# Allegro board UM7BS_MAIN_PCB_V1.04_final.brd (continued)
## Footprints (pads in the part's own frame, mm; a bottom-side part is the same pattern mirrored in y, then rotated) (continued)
QFN40P600X600-48AN
  oval 0.7x0.2 smd: 1(-2.9,2.2) 2(-2.9,1.8) 3(-2.9,1.4) 4(-2.9,1) 5(-2.9,0.6) 6(-2.9,0.2) 7(-2.9,-0.2) 8(-2.9,-0.6) 9(-2.9,-1) 10(-2.9,-1.4) 11(-2.9,-1.8) 12(-2.9,-2.2) 25(2.9,-2.2) 26(2.9,-1.8) 27(2.9,-1.4) 28(2.9,-1) 29(2.9,-0.6) 30(2.9,-0.2) 31(2.9,0.2) 32(2.9,0.6) 33(2.9,1) 34(2.9,1.4) 35(2.9,1.8) 36(2.9,2.2)
  oval 0.2x0.7 smd: 13(-2.2,-2.9) 14(-1.8,-2.9) 15(-1.4,-2.9) 16(-1,-2.9) 17(-0.6,-2.9) 18(-0.2,-2.9) 19(0.2,-2.9) 20(0.6,-2.9) 21(1,-2.9) 22(1.4,-2.9) 23(1.8,-2.9) 24(2.2,-2.9) 37(2.2,2.9) 38(1.8,2.9) 39(1.4,2.9) 40(1,2.9) 41(0.6,2.9) 42(0.2,2.9) 43(-0.2,2.9) 44(-0.6,2.9) 45(-1,2.9) 46(-1.4,2.9) 47(-1.8,2.9) 48(-2.2,2.9)
  rect 3.6x4.05 smd: E1(0,0)
QFN40P600X600-48N
  oval 0.7x0.2 smd: 1(-2.9,2.2) 2(-2.9,1.8) 3(-2.9,1.4) 4(-2.9,1) 5(-2.9,0.6) 6(-2.9,0.2) 7(-2.9,-0.2) 8(-2.9,-0.6) 9(-2.9,-1) 10(-2.9,-1.4) 11(-2.9,-1.8) 12(-2.9,-2.2) 25(2.9,-2.2) 26(2.9,-1.8) 27(2.9,-1.4) 28(2.9,-1) 29(2.9,-0.6) 30(2.9,-0.2) 31(2.9,0.2) 32(2.9,0.6) 33(2.9,1) 34(2.9,1.4) 35(2.9,1.8) 36(2.9,2.2)
  oval 0.2x0.7 smd: 13(-2.2,-2.9) 14(-1.8,-2.9) 15(-1.4,-2.9) 16(-1,-2.9) 17(-0.6,-2.9) 18(-0.2,-2.9) 19(0.2,-2.9) 20(0.6,-2.9) 21(1,-2.9) 22(1.4,-2.9) 23(1.8,-2.9) 24(2.2,-2.9) 37(2.2,2.9) 38(1.8,2.9) 39(1.4,2.9) 40(1,2.9) 41(0.6,2.9) 42(0.2,2.9) 43(-0.2,2.9) 44(-0.6,2.9) 45(-1,2.9) 46(-1.4,2.9) 47(-1.8,2.9) 48(-2.2,2.9)
  rect 4.3x4.3 smd: E1(0,0)
QFN40P700X700-56AN
  oval 0.7x0.2 smd: 1(-3.4,2.6) 2(-3.4,2.2) 3(-3.4,1.8) 4(-3.4,1.4) 5(-3.4,1) 6(-3.4,0.6) 7(-3.4,0.2) 8(-3.4,-0.2) 9(-3.4,-0.6) 10(-3.4,-1) 11(-3.4,-1.4) 12(-3.4,-1.8) 13(-3.4,-2.2) 14(-3.4,-2.6) 29(3.4,-2.6) 30(3.4,-2.2) 31(3.4,-1.8) 32(3.4,-1.4) 33(3.4,-1) 34(3.4,-0.6) 35(3.4,-0.2) 36(3.4,0.2) 37(3.4,0.6) 38(3.4,1) 39(3.4,1.4) 40(3.4,1.8) 41(3.4,2.2) 42(3.4,2.6)
  oval 0.2x0.7 smd: 15(-2.6,-3.4) 16(-2.2,-3.4) 17(-1.8,-3.4) 18(-1.4,-3.4) 19(-1,-3.4) 20(-0.6,-3.4) 21(-0.2,-3.4) 22(0.2,-3.4) 23(0.6,-3.4) 24(1,-3.4) 25(1.4,-3.4) 26(1.8,-3.4) 27(2.2,-3.4) 28(2.6,-3.4) 43(2.6,3.4) 44(2.2,3.4) 45(1.8,3.4) 46(1.4,3.4) 47(1,3.4) 48(0.6,3.4) 49(0.2,3.4) 50(-0.2,3.4) 51(-0.6,3.4) 52(-1,3.4) 53(-1.4,3.4) 54(-1.8,3.4) 55(-2.2,3.4) 56(-2.6,3.4)
  rect 4.1x4.8 smd: E1(0,0)
QFN40P800X800-64N
  oval 0.8x0.2 smd: 1(-3.9,3) 2(-3.9,2.6) 3(-3.9,2.2) 4(-3.9,1.8) 5(-3.9,1.4) 6(-3.9,1) 7(-3.9,0.6) 8(-3.9,0.2) 9(-3.9,-0.2) 10(-3.9,-0.6) 11(-3.9,-1) 12(-3.9,-1.4) 13(-3.9,-1.8) 14(-3.9,-2.2) 15(-3.9,-2.6) 16(-3.9,-3) 33(3.9,-3) 34(3.9,-2.6) 35(3.9,-2.2) 36(3.9,-1.8) 37(3.9,-1.4) 38(3.9,-1) 39(3.9,-0.6) 40(3.9,-0.2) 41(3.9,0.2) 42(3.9,0.6) 43(3.9,1) 44(3.9,1.4) 45(3.9,1.8) 46(3.9,2.2) 47(3.9,2.6) 48(3.9,3)
  oval 0.2x0.8 smd: 17(-3,-3.9) 18(-2.6,-3.9) 19(-2.2,-3.9) 20(-1.8,-3.9) 21(-1.4,-3.9) 22(-1,-3.9) 23(-0.6,-3.9) 24(-0.2,-3.9) 25(0.2,-3.9) 26(0.6,-3.9) 27(1,-3.9) 28(1.4,-3.9) 29(1.8,-3.9) 30(2.2,-3.9) 31(2.6,-3.9) 32(3,-3.9) 49(3,3.9) 50(2.6,3.9) 51(2.2,3.9) 52(1.8,3.9) 53(1.4,3.9) 54(1,3.9) 55(0.6,3.9) 56(0.2,3.9) 57(-0.2,3.9) 58(-0.6,3.9) 59(-1,3.9) 60(-1.4,3.9) 61(-1.8,3.9) 62(-2.2,3.9) 63(-2.6,3.9) 64(-3,3.9)
  rect 5.7x5.7 smd: E1(0,0)
QFN50P400X400-24BN
  oval 0.8x0.28 smd: 1(-2,1.25) 2(-2,0.75) 3(-2,0.25) 4(-2,-0.25) 5(-2,-0.75) 6(-2,-1.25) 13(2,-1.25) 14(2,-0.75) 15(2,-0.25) 16(2,0.25) 17(2,0.75) 18(2,1.25)
  oval 0.28x0.8 smd: 7(-1.25,-2) 8(-0.75,-2) 9(-0.25,-2) 10(0.25,-2) 11(0.75,-2) 12(1.25,-2) 19(1.25,2) 20(0.75,2) 21(0.25,2) 22(-0.25,2) 23(-0.75,2) 24(-1.25,2)
  rect 2.5x2.5 smd: E1(0,0)
RC0402N
  rect 0.55x0.5 smd: 1(-0.475,0) 2(0.475,0)
RC0603N
  rect 0.8x0.8 smd: 1(-0.75,0) 2(0.75,0)
RC0805N
  rect 1x1.2 smd: 1(-1,0) 2(1,0)
RC1206N
  rect 1.2x1.6 smd: 1(-1.6,0) 2(1.6,0)
SMD-BATTERY-2900P-2N
  rect 3x4.2 smd: 1(14.5,0) 2(-14.5,0)
SMD-CN-50P-20N-H
  oval 0.28x1.25 smd: 1(-4.75,2.325) 2(-4.25,2.325) 3(-3.75,2.325) 4(-3.25,2.325) 5(-2.75,2.325) 6(-2.25,2.325) 7(-1.75,2.325) 8(-1.25,2.325) 9(-0.75,2.325) 10(-0.25,2.325) 11(0.25,2.325) 12(0.75,2.325) 13(1.25,2.325) 14(1.75,2.325) 15(2.25,2.325) 16(2.75,2.325) 17(3.25,2.325) 18(3.75,2.325) 19(4.25,2.325) 20(4.75,2.325)
  rect 2x3.4 smd: E1(-6.44,0.4) E2(6.44,0.4)
SMD-CN-100P-2N-V-CB
  rect 0.6x1.5 smd: 1(0.5,2.55) 2(-0.5,2.55)
  rect 1.2x1.8 smd: E1(-1.8,0) E2(1.8,0)
SMD-CN-100P-4N-V-CB
  rect 0.6x1.5 smd: 1(1.5,2.55) 2(0.5,2.55) 3(-0.5,2.55) 4(-1.5,2.55)
  rect 1.2x1.8 smd: E1(-2.8,0) E2(2.8,0)
SMD-CN-100P-6N-H
  rect 0.6x1.55 smd: 1(-2.5,3.875) 2(-1.5,3.875) 3(-0.5,3.875) 4(0.5,3.875) 5(1.5,3.875) 6(2.5,3.875)
  rect 1.2x2 smd: E1(-3.8,0) E2(3.8,0)
SMD-CN-100P-40AN-H
  rect 0.6x1.6 smd: 1(-9.5,-2.9) 2(-8.5,-2.9) 3(-7.5,-2.9) 4(-6.5,-2.9) 5(-5.5,-2.9) 6(-4.5,-2.9) 7(-3.5,-2.9) 8(-2.5,-2.9) 9(-1.5,-2.9) 10(-0.5,-2.9) 11(0.5,-2.9) 12(1.5,-2.9) 13(2.5,-2.9) 14(3.5,-2.9) 15(4.5,-2.9) 16(5.5,-2.9) 17(6.5,-2.9) 18(7.5,-2.9) 19(8.5,-2.9) 20(9.5,-2.9) 21(9.5,2.9) 22(8.5,2.9) 23(7.5,2.9) 24(6.5,2.9) 25(5.5,2.9) 26(4.5,2.9) 27(3.5,2.9) 28(2.5,2.9) 29(1.5,2.9) 30(0.5,2.9) 31(-0.5,2.9) 32(-1.5,2.9) 33(-2.5,2.9) 34(-3.5,2.9) 35(-4.5,2.9) 36(-5.5,2.9) 37(-6.5,2.9) 38(-7.5,2.9) 39(-8.5,2.9) 40(-9.5,2.9)
  rect 1.5x2.3 smd: E1(-11.5,-1.3) E2(11.5,-1.3)
SMD-CN-125P-2WBN
  rect 0.8x1.5 smd: 1(-0.625,2.49) 2(0.625,2.49)
  rect 2x2.5 smd: E1(-3.175,0) E2(3.175,0)
SMD-CN-200P-8N
  rect 1x3 smd: 1(-3,-2.25) 2(-3,2.25) 3(-1,-2.25) 4(-1,2.25) 5(1,-2.25) 6(1,2.25) 7(3,-2.25) 8(3,2.25)
SMD-DDR-60X1020P-204N-R
  round 1.1 hole 1.1 unplated: (-33.4,0)
  round 1.6 hole 1.6 unplated: (33.4,0)
  rect 0.35x2 smd: 1(31.65,4.1) 2(31.35,-4.1) 3(31.05,4.1) 4(30.75,-4.1) 5(30.45,4.1) 6(30.15,-4.1) 7(29.85,4.1) 8(29.55,-4.1) 9(29.25,4.1) 10(28.95,-4.1) 11(28.65,4.1) 12(28.35,-4.1) 13(28.05,4.1) 14(27.75,-4.1) 15(27.45,4.1) 16(27.15,-4.1) 17(26.85,4.1) 18(26.55,-4.1) 19(26.25,4.1) 20(25.95,-4.1) 21(25.65,4.1) 22(25.35,-4.1) 23(25.05,4.1) 24(24.75,-4.1) 25(24.45,4.1) 26(24.15,-4.1) 27(23.85,4.1) 28(23.55,-4.1) 29(23.25,4.1) 30(22.95,-4.1) 31(22.65,4.1) 32(22.35,-4.1) 33(22.05,4.1) 34(21.75,-4.1) 35(21.45,4.1) 36(21.15,-4.1) 37(20.85,4.1) 38(20.55,-4.1) 39(20.25,4.1) 40(19.95,-4.1) 41(19.65,4.1) 42(19.35,-4.1) 43(19.05,4.1) 44(18.75,-4.1) 45(18.45,4.1) 46(18.15,-4.1) 47(17.85,4.1) 48(17.55,-4.1) 49(17.25,4.1) 50(16.95,-4.1) 51(16.65,4.1) 52(16.35,-4.1) 53(16.05,4.1) 54(15.75,-4.1) 55(15.45,4.1) 56(15.15,-4.1) 57(14.85,4.1) 58(14.55,-4.1) 59(14.25,4.1) 60(13.95,-4.1) 61(13.65,4.1) 62(13.35,-4.1) 63(13.05,4.1) 64(12.75,-4.1) 65(12.45,4.1) 66(12.15,-4.1) 67(11.85,4.1) 68(11.55,-4.1) 69(11.25,4.1) 70(10.95,-4.1) 71(10.65,4.1) 72(10.35,-4.1) 73(7.65,4.1) 74(7.35,-4.1) 75(7.05,4.1) 76(6.75,-4.1) 77(6.45,4.1) 78(6.15,-4.1) 79(5.85,4.1) 80(5.55,-4.1) 81(5.25,4.1) 82(4.95,-4.1) 83(4.65,4.1) 84(4.35,-4.1) 85(4.05,4.1) 86(3.75,-4.1) 87(3.45,4.1) 88(3.15,-4.1) 89(2.85,4.1) 90(2.55,-4.1) 91(2.25,4.1) 92(1.95,-4.1) 93(1.65,4.1) 94(1.35,-4.1) 95(1.05,4.1) 96(0.75,-4.1) 97(0.45,4.1) 98(0.15,-4.1) 99(-0.15,4.1) 100(-0.45,-4.1) 101(-0.75,4.1) 102(-1.05,-4.1) 103(-1.35,4.1) 104(-1.65,-4.1) 105(-1.95,4.1) 106(-2.25,-4.1) 107(-2.55,4.1) 108(-2.85,-4.1) 109(-3.15,4.1) 110(-3.45,-4.1) 111(-3.75,4.1) 112(-4.05,-4.1) 113(-4.35,4.1) 114(-4.65,-4.1) 115(-4.95,4.1) 116(-5.25,-4.1) 117(-5.55,4.1) 118(-5.85,-4.1) 119(-6.15,4.1) 120(-6.45,-4.1) 121(-6.75,4.1) 122(-7.05,-4.1) 123(-7.35,4.1) 124(-7.65,-4.1) 125(-7.95,4.1) 126(-8.25,-4.1) 127(-8.55,4.1) 128(-8.85,-4.1) 129(-9.15,4.1) 130(-9.45,-4.1) 131(-9.75,4.1) 132(-10.05,-4.1) 133(-10.35,4.1) 134(-10.65,-4.1) 135(-10.95,4.1) 136(-11.25,-4.1) 137(-11.55,4.1) 138(-11.85,-4.1) 139(-12.15,4.1) 140(-12.45,-4.1) 141(-12.75,4.1) 142(-13.05,-4.1) 143(-13.35,4.1) 144(-13.65,-4.1) 145(-13.95,4.1) 146(-14.25,-4.1) 147(-14.55,4.1) 148(-14.85,-4.1) 149(-15.15,4.1) 150(-15.45,-4.1) 151(-15.75,4.1) 152(-16.05,-4.1) 153(-16.35,4.1) 154(-16.65,-4.1) 155(-16.95,4.1) 156(-17.25,-4.1) 157(-17.55,4.1) 158(-17.85,-4.1) 159(-18.15,4.1) 160(-18.45,-4.1) 161(-18.75,4.1) 162(-19.05,-4.1) 163(-19.35,4.1) 164(-19.65,-4.1) 165(-19.95,4.1) 166(-20.25,-4.1) 167(-20.55,4.1) 168(-20.85,-4.1) 169(-21.15,4.1) 170(-21.45,-4.1) 171(-21.75,4.1) 172(-22.05,-4.1) 173(-22.35,4.1) 174(-22.65,-4.1) 175(-22.95,4.1) 176(-23.25,-4.1) 177(-23.55,4.1) 178(-23.85,-4.1) 179(-24.15,4.1) 180(-24.45,-4.1) 181(-24.75,4.1) 182(-25.05,-4.1) 183(-25.35,4.1) 184(-25.65,-4.1) 185(-25.95,4.1) 186(-26.25,-4.1) 187(-26.55,4.1) 188(-26.85,-4.1) 189(-27.15,4.1) 190(-27.45,-4.1) 191(-27.75,4.1) 192(-28.05,-4.1) 193(-28.35,4.1) 194(-28.65,-4.1) 195(-28.95,4.1) 196(-29.25,-4.1) 197(-29.55,4.1) 198(-29.85,-4.1) 199(-30.15,4.1) 200(-30.45,-4.1) 201(-30.75,4.1) 202(-31.05,-4.1) 203(-31.35,4.1) 204(-31.65,-4.1)
  rect 3.6x4.6 smd: E1(-32.8,-12) E2(32.8,-12)
SMD-M2PCIE-50X750P-75AN
  round 0.254 hole 1.092 unplated: (-10,-1.499)
  round 0.254 hole 1.6 unplated: (10,-1.499)
  rect 0.305x1.575 smd: 1(-9.25,3.763) 2(-9,-3.763) 3(-8.75,3.763) 4(-8.5,-3.763) 5(-8.25,3.763) 6(-8,-3.763) 7(-7.75,3.763) 8(-7.5,-3.763) 9(-7.25,3.763) 10(-7,-3.763) 11(-6.75,3.763) 12(-6.5,-3.763) 13(-6.25,3.763) 14(-6,-3.763) 15(-5.75,3.763) 16(-5.5,-3.763) 17(-5.25,3.763) 18(-5,-3.763) 19(-4.75,3.763) 20(-4.5,-3.763) 21(-4.25,3.763) 22(-4,-3.763) 23(-3.75,3.763) 24(-3.5,-3.763) 25(-3.25,3.763) 26(-3,-3.763) 27(-2.75,3.763) 28(-2.5,-3.763) 29(-2.25,3.763) 30(-2,-3.763) 31(-1.75,3.763) 32(-1.5,-3.763) 33(-1.25,3.763) 34(-1,-3.763) 35(-0.75,3.763) 36(-0.5,-3.763) 37(-0.25,3.763) 38(0,-3.763) 39(0.25,3.763) 40(0.5,-3.763) 41(0.75,3.763) 42(1,-3.763) 43(1.25,3.763) 44(1.5,-3.763) 45(1.75,3.763) 46(2,-3.763) 47(2.25,3.763) 48(2.5,-3.763) 49(2.75,3.763) 50(3,-3.763) 51(3.25,3.763) 52(3.5,-3.763) 53(3.75,3.763) 54(4,-3.763) 55(4.25,3.763) 56(4.5,-3.763) 57(4.75,3.763) 58(5,-3.763) 59(5.25,3.763) 60(5.5,-3.763) 61(5.75,3.763) 62(6,-3.763) 63(6.25,3.763) 64(6.5,-3.763) 65(6.75,3.763) 66(7,-3.763) 67(7.25,3.763) 68(7.5,-3.763) 69(7.75,3.763) 70(8,-3.763) 71(8.25,3.763) 72(8.5,-3.763) 73(8.75,3.763) 74(9,-3.763) 75(9.25,3.763)
  rect 1.219x2.769 smd: E1(-10.39,3.001) E2(10.39,3.001)
SMD-M2PCIE-50X750P-75BN
  round 0.254 hole 1.092 unplated: (-10,-1.499)
  round 0.254 hole 1.6 unplated: (10,-1.499)
  rect 0.305x1.575 smd: 1(-9.25,3.763) 2(-9,-3.763) 3(-8.75,3.763) 4(-8.5,-3.763) 5(-8.25,3.763) 6(-8,-3.763) 7(-7.75,3.763) 8(-7.5,-3.763) 9(-7.25,3.763) 10(-7,-3.763) 11(-6.75,3.763) 12(-6.5,-3.763) 13(-6.25,3.763) 14(-6,-3.763) 15(-5.75,3.763) 16(-5.5,-3.763) 17(-5.25,3.763) 18(-5,-3.763) 19(-4.75,3.763) 20(-4.5,-3.763) 21(-4.25,3.763) 22(-4,-3.763) 23(-3.75,3.763) 24(-3.5,-3.763) 25(-3.25,3.763) 26(-3,-3.763) 27(-2.75,3.763) 28(-2.5,-3.763) 29(-2.25,3.763) 30(-2,-3.763) 31(-1.75,3.763) 32(-1.5,-3.763) 33(-1.25,3.763) 34(-1,-3.763) 35(-0.75,3.763) 36(-0.5,-3.763) 37(-0.25,3.763) 38(0,-3.763) 39(0.25,3.763) 40(0.5,-3.763) 41(0.75,3.763) 42(1,-3.763) 43(1.25,3.763) 44(1.5,-3.763) 45(1.75,3.763) 46(2,-3.763) 47(2.25,3.763) 48(2.5,-3.763) 49(2.75,3.763) 50(3,-3.763) 51(3.25,3.763) 52(3.5,-3.763) 53(3.75,3.763) 54(4,-3.763) 55(4.25,3.763) 56(4.5,-3.763) 57(4.75,3.763) 58(5,-3.763) 67(7.25,3.763) 68(7.5,-3.763) 69(7.75,3.763) 70(8,-3.763) 71(8.25,3.763) 72(8.5,-3.763) 73(8.75,3.763) 74(9,-3.763) 75(9.25,3.763)
  rect 1.219x2.769 smd: E1(-10.39,3.001) E2(10.39,3.001)
SMD-SATA-127P-22AN-L-KX
  round 1.4 hole 1.4 unplated: (-17,-1.35) (17,-1.35)
  oval 1.6x3.3 hole 1x2.6: E1(-18.71,1.05) E2(18.71,1.05)
  rect 0.9x2.6 smd: P1(-1.905,1.05) P2(-0.635,1.05) P3(0.635,1.05) P4(1.905,1.05) P5(3.175,1.05) P6(4.445,1.05) P7(5.715,1.05) P8(6.985,1.05) P9(8.255,1.05) P10(9.525,1.05) P11(10.795,1.05) P12(12.065,1.05) P13(13.335,1.05) P14(14.605,1.05) P15(15.875,1.05) S1(-15.875,1.05) S2(-14.605,1.05) S3(-13.335,1.05) S4(-12.065,1.05) S5(-10.795,1.05) S6(-9.525,1.05) S7(-8.255,1.05)
SMD-SD-250P-9N
  round 1 hole 1 unplated: (-11.45,6.5)
  round 1.5 hole 1.5 unplated: (9.53,6.5)
  rect 0.7x1.9 smd: 1(6.8,9.25) 2(4.3,9.25) 3(1.8,9.25) 4(-0.7,9.25) 5(-3.2,9.25) 6(-5.7,9.25) 7(-8.2,9.25) 8(-9.83,9.25) 9(9.3,9.25) 10(-12.37,9.25) 11(-11.08,9.25)
  rect 1.6x1.6 smd: E1(-14.05,7.55) E2(11.75,7.55) E3(-14.05,-6.65) E4(14.05,-6.65)
SMD-TRANSF-127P-16N
  rect 1.9x0.8 smd: 1(-4.2,4.445) 2(-4.2,3.175) 3(-4.2,1.905) 4(-4.2,0.635) 5(-4.2,-0.635) 6(-4.2,-1.905) 7(-4.2,-3.175) 8(-4.2,-4.445) 9(4.2,-4.445) 10(4.2,-3.175) 11(4.2,-1.905) 12(4.2,-0.635) 13(4.2,0.635) 14(4.2,1.905) 15(4.2,3.175) 16(4.2,4.445)
SMD-USB-100P-9AN
  rect 0.7x1.65 smd: 1(-3,1) 2(-1,1) 3(1,1) 4(3,1) 5(4,1) 6(2,1) 7(0,1) 8(-2,1) 9(-4,1)
  oval 1.6x3.4 hole 0.6x2.4: E1(-7.9,0) E2(7.9,0)
  rect 1.7x2.3 smd: E3(-7.68,-4.2) E4(7.68,-4.2)
SOD0806N
  rect 0.4x0.35 smd: N(-0.45,0) P(0.45,0)
SOD1713N
  rect 0.8x0.6 smd: N(1.25,0) P(-1.25,0)
SOD2514N
  rect 1.2x0.5 smd: N(-1.15,0) P(1.15,0)
SOD2818N
  rect 2.2x1.4 smd: N(1,0)
  rect 0.9x1.4 smd: P(-1.65,0)
SOD5225N
  rect 2x2 smd: N(-2.095,0) P(2.095,0)
SOD5336N
  rect 2.5x2.3 smd: N(2.15,0) P(-2.15,0)
SOIC127P600-8N
  rect 1.9x0.6 smd: 1(-2.55,1.905) 2(-2.55,0.635) 3(-2.55,-0.635) 4(-2.55,-1.905) 5(2.55,-1.905) 6(2.55,-0.635) 7(2.55,0.635) 8(2.55,1.905)
SOIC127P800-8N
  rect 1.8x0.6 smd: 1(-3.6,1.905) 2(-3.6,0.635) 3(-3.6,-0.635) 4(-3.6,-1.905) 5(3.6,-1.905) 6(3.6,-0.635) 7(3.6,0.635) 8(3.6,1.905)
SON35P100-8N
  oval 0.55x0.2 smd: 1(-0.46,0.525) 2(-0.46,0.174) 3(-0.46,-0.176) 4(-0.46,-0.526) 5(0.46,-0.526) 6(0.46,-0.176) 7(0.46,0.174) 8(0.46,0.525)
SON50P200X200-8N
  oval 0.6x0.25 smd: 1(-1,0.749) 2(-1,0.249) 3(-1,-0.251) 4(-1,-0.751) 5(1,-0.751) 6(1,-0.251) 7(1,0.249) 8(1,0.749)
  rect 0.9x1.6 smd: E1(0,0)
SON127P500X600-8AN
  oval 0.9x0.6 smd: 1(-2.85,1.905) 2(-2.85,0.635) 3(-2.85,-0.635) 4(-2.85,-1.905) 5(2.85,-1.905) 6(2.85,-0.635) 7(2.85,0.635) 8(2.85,1.905)
  rect 3.4x4 smd: E1(0,0)
SOP35P100-3N
  rect 0.3x0.3 smd: 1(-0.35,-0.425) 2(0.35,-0.425) 3(0,0.425)
SOT65P190-5N
  oval 1.1x0.35 smd: 1(-0.95,0.65) 2(-0.95,0) 3(-0.95,-0.65) 4(0.95,-0.65) 5(0.95,0.65)
SOT65P210-3N
  rect 1.2x0.45 smd: 1(-0.9,0.65) 2(-0.9,-0.65) 3(0.9,0)
SOT65P210-5N
  rect 1.1x0.4 smd: 1(-0.95,0.65) 2(-0.95,0) 3(-0.95,-0.65) 4(0.95,-0.65) 5(0.95,0.65)
SOT65P210-6N
  rect 1.08x0.35 smd: 1(-1,0.65) 2(-1,0) 3(-1,-0.65) 4(1,-0.65) 5(1,0) 6(1,0.65)
SOT95P240-3N
  rect 1.4x0.6 smd: 1(-1,0.95) 2(-1,-0.95) 3(1,0)
SOT95P280-3N
  rect 1.35x0.6 smd: 1(-1.25,0.95) 2(-1.25,-0.95) 3(1.25,0)
SOT95P280-5N
  rect 1.3x0.6 smd: 1(-1.25,0.95) 2(-1.25,0) 3(-1.25,-0.95) 4(1.25,-0.95) 5(1.25,0.95)
SOT229P990-3N
  rect 1x2.2 smd: 1(-2.29,-3.35) 2(2.29,-3.35)
  rect 5.5x5.3 smd: 3(0,3.15)
SSOP65P780-28N
  rect 1.4x0.3 smd: 1(-3.35,4.225) 2(-3.35,3.575) 3(-3.35,2.925) 4(-3.35,2.275) 5(-3.35,1.625) 6(-3.35,0.975) 7(-3.35,0.325) 8(-3.35,-0.325) 9(-3.35,-0.975) 10(-3.35,-1.625) 11(-3.35,-2.275) 12(-3.35,-2.925) 13(-3.35,-3.575) 14(-3.35,-4.225) 15(3.35,-4.225) 16(3.35,-3.575) 17(3.35,-2.925) 18(3.35,-2.275) 19(3.35,-1.625) 20(3.35,-0.975) 21(3.35,-0.325) 22(3.35,0.325) 23(3.35,0.975) 24(3.35,1.625) 25(3.35,2.275) 26(3.35,2.925) 27(3.35,3.575) 28(3.35,4.225)
SW_330X390P_4N
  rect 1x0.7 smd: 1(-1.95,1.65) 2(-1.95,-1.65) 3(1.95,1.65) 4(1.95,-1.65)
TDFN50P300X300-10N
  oval 0.65x0.25 smd: 1(-1.325,1) 2(-1.325,0.5) 3(-1.325,0) 4(-1.325,-0.5) 5(-1.325,-1) 6(1.325,-1) 7(1.325,-0.5) 8(1.325,0) 9(1.325,0.5) 10(1.325,1)
  rect 1.5x2.5 smd: E1(0,0)
TEST120
  round 1.2 smd: 1(0,0)
TH-CN-200P-2N-H
  round 1.4 hole 0.8: 1(-1,0) 2(1,0)
TH-DCIN-540P-3N
  round 1.3 hole 1.3 unplated: (-4.25,4.5) (4.25,-4.5)
  oval 2x3.5 hole 0.9x2.5: B(-4,1)
  oval 3.5x2 hole 2.5x0.9: C(-2,-4.4) D(2.6,-2)
TH-EARPHONE-330X400P-5N
  round 1.1 hole 1.1 unplated: (0,-2.55)
  oval 2.1x1.2 hole 1.5x0.6: 2(0,2.55)
  oval 1.2x2.1 hole 0.6x1.5: 3(-4,1.65) 4(4,1.65) 5(-2.5,-1.65) 6(2.5,-1.65)
TH-RJ45-127P-8N
  round 3.2 hole 3.2 unplated: (-5.715,1.1) (5.715,1.1)
  round 1.05 hole 0.7: 1(-4.445,7.45) 2(-3.175,7.45) 3(-1.905,7.45) 4(-0.635,7.45) 5(0.635,7.45) 6(1.905,7.45) 7(3.175,7.45) 8(4.445,7.45)
  round 2.6 hole 1.6: E1(-7.875,4.99) E2(7.875,4.99)
TH-SW-420P-2N
  round 1 hole 1 unplated: (-1.15,0) (1.15,0)
  rect 1.2x1.5 smd: 1(-2.1,1) 2(2.1,1)
  rect 1.3x1.2 smd: E1(-3.525,-0.8) E2(3.525,-0.8)
TH-USB-250PX200P-4BN
  round 1.55 hole 0.95: 1(-3.5,0.81) 2(-1,0.81) 3(1,0.81) 4(3.5,0.81)
  oval 1.2x2.1 hole 0.6x1.5: E1(-6.4,0.21) E2(6.4,0.21)
THR-CPR50-630X1100N
  round 1.5 hole 0.7: 1(-1.25,0) 2(1.25,0)
TSSOP65P640-16AN
  rect 1.6x0.35 smd: 1(-3,2.275) 2(-3,1.625) 3(-3,0.975) 4(-3,0.325) 5(-3,-0.325) 6(-3,-0.975) 7(-3,-1.625) 8(-3,-2.275) 9(3,-2.275) 10(3,-1.625) 11(3,-0.975) 12(3,-0.325) 13(3,0.325) 14(3,0.975) 15(3,1.625) 16(3,2.275)
  rect 3x2.8 smd: E1(0,0)
unnamed
  round 2 hole 2 unplated: (0,0)
UQFN40P200X170-12N
  oval 0.7x0.4 smd: 1(-0.7,0.9)
  oval 0.7x0.2 smd: 2(-0.7,0.401) 3(-0.7,0.002) 4(-0.7,-0.399) 5(-0.7,-0.799) 7(0.7,-0.799) 8(0.7,-0.399) 9(0.7,0.002) 10(0.7,0.401) 11(0.7,0.801)
  oval 0.2x0.7 smd: 6(0,-0.85) 12(0,0.85)
VSOP127P790-8N
  rect 1.6x0.6 smd: 1(-3.44,1.905) 2(-3.44,0.635) 3(-3.44,-0.635) 4(-3.44,-1.905) 5(3.44,-1.905) 6(3.44,-0.635) 7(3.44,0.635) 8(3.44,1.905)

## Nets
3.3V_IN: C149.2 FB1.2 FB2.1 R172.1 R173.2 R175.1 U9.24(V33)
+V1.2A: C201.2 R670.1 U11.49(LDOA3)
+V1.05A: C42.2 C43.2 C44.2 C45.2 C46.2 C47.2 C48.2 C52.2 C53.2 C54.1 C55.1 C56.2 C57.2 C58.2 C68.2 C69.2 C70.2 C71.2 C72.2 C73.1 C74.1 C75.1 C76.1 C77.1 C106.2 C239.1 C240.1 C241.1 C242.1 CP3.1 L7.1 R111.2 R843.1 U1.AA32(UNCORE_V1P15_S0IX1) U1.AA33(UNCORE_V1P15_S0IX2) U1.AA35(UNCORE_V1P15_S0IX3) U1.AA36(UNCORE_V1P15_S0IX4) U1.AC32(UNCORE_V1P15_S0IX5) U1.AM21(DDR_V1P05A_G31) U1.AM22(DDR_V1P05A_G32) U1.AM32(DDR_V1P05A_G33) U1.AM33(DDR_V1P05A_G34) U1.AN22(DDR_V1P05A_G35) U1.AN32(DDR_V1P05A_G36) U1.G10(FUSE0_V1P05A_G3) U1.H10(FUSE1_V1P05A_G4) U1.N18(FUSE3_V1P05A_G5) U1.U19(FUSE_V1P05A_G3) U1.U22(SATA_V1P05A_G31) U1.U24(SATA_V1P05A_G32) U1.U27(USB3_V1P05A_G31) U1.V18(ICLK_GND_OFF1) U1.V19(ICLK_GND_OFF2) U1.V22(PCIE_V1P05A_G31) U1.V24(PCIE_V1P05A_G32) U1.V27(USB3_V1P05A_G32) U1.V29(USBSSIC_V1P05A_G3) U1.V33(UNCORE_V1P15_S0IX6) U1.Y30(UNCORE_V1P15_S0IX7) U1.Y32(UNCORE_V1P15_S0IX8) U1.Y33(UNCORE_V1P15_S0IX9) U1.Y35(UNCORE_V1P15_S0IX10)
+V1.5S: C362.2 C557.1 R137.1 R330.2 R556.2 U46.4(VOUT)
+V1.5S_AUDIO: FB11.2 R330.1 R344.2
+V1.8A: C9.2 C14.1 C21.1 C96.2 C97.2 C103.2 C107.2 C108.2 C109.2 C110.2 C111.2 C194.2 C234.2 C249.1 C250.1 C251.1 C252.1 C413.1 C418.1 C420.1 C435.1 C527.1 C2837.1 D1.P L8.1 Q6.1(G) Q7.1(G) Q52.1(G) Q53.1(G) R14.2 R18.2 R26.2 R27.2 R28.2 R29.2 R42.1 R43.2 R51.1 R53.1 R54.1 R55.2 R58.1 R61.1 R62.2 R64.2 R65.2 R66.1 R67.2 R68.2 R71.1 R73.2 R88.2 R89.2 R90.2 R108.2 R115.2 R119.2 R122.2 R125.1 R127.1 R134.2 R138.1 R141.2 R163.1 R169.1 R196.2 R227.2 R228.2 R229.2 R234.1 R386.1 R391.1 R401.1 R402.1 R409.2 R414.2 R416.2 R427.1 R434.2 R441.2 R572.2 R573.2 R844.1 R3108.2 U1.AA29(USB_V1P8A_G3) U1.AD33(GPIO_V1P8A_G31) U1.AF33(GPIO_V1P8A_G32) U1.AK18(GPIO_V1P8A_G33) U1.AK19(GPIO_V1P8A_G34) U1.U16(FUSE_V1P8A_G3) U1.Y18(GPIO_V1P8A_G35) U3.1(VIN1) U3.2(VIN2) U5.1(VCCA) U6.1(VCCA) U11.18(PVINSWB1_B2) U11.50(PVINLDOA2_A3) U29.1(VCCA) U30.1(VCCA) U32.1(VCCA) U46.3(VIN) U53.7(VIN1) U53.8(VIN2) U53.9(VIN3) U2525.7(VIN1) U2525.8(VIN2) U2525.9(VIN3)
+V1.8A_SPI: C8.2 D1.N R40.2 R41.2 R42.2 R568.2 U2.8(VCC) U3.7(VOUT2) U3.8(VOUT1) U4.8(VCC)
+V1.8S: C235.2 D44.P FB10.2 R22.2 R72.2 R343.2 R575.1 U11.19(SWB2)
+V1.8U: C233.2 U11.17(SWB1)
+V1.15A: C59.2 C60.2 C61.2 C62.2 C63.2 C64.2 C65.2 C66.2 C67.2 C2835.1 R213.2 R746.2 U1.AJ35(FUSE_V1P15_S0IX1) U1.AK21(DDI_V1P15_S0IX1) U1.AK30(CORE_V1P15_S0IX1) U1.AK33(FUSE_V1P15_S0IX2) U1.AK35(CORE_V1P15_S0IX2) U1.AK36(CORE_V1P15_S0IX3) U1.AM19(DDI_V1P15_S0IX2) U1.AM29(CORE_V1P15_S0IX4) U2525.1(VOUT1) U2525.2(VOUT2) U2525.3(VOUT3)
+V1.15S: C193.2 R213.1 U11.51(LDOA2)
+V1.24A: C78.2 C79.2 C83.2 C84.2 C85.2 C86.2 C89.2 C90.2 C95.2 C2834.1 R136.1 R139.1 R142.1 R670.2 R3107.1 U1.AC30(CORE_VSFR_G37) U1.AC36(CORE_VSFR_G31) U1.AD35(CORE_VSFR_G32) U1.AD38(CORE_VSFR_G33) U1.AF35(CORE_VSFR_G34) U1.H44(USB_VDDQ_G31) U1.P38(CORE_VSFR_G35) U1.U35(USB_VDDQ_G32) U1.V30(CORE_VSFR_G36) U1.V35(USB_VDDQ_G33) U1.V36(DDI_VDDQ_G31) U1.Y25(ICLK_VSFR_G31) U1.Y27(ICLK_VSFR_G32) U1.Y36(DDI_VDDQ_G32) U53.1(VOUT1) U53.2(VOUT2) U53.3(VOUT3)
+V1P8A_EMMC: C144.1 C145.1 D44.N R163.2 R575.2 R576.1 U8.AA3(VDD4) U8.AA5(VDD5) U8.K6(VDD1) U8.W4(VDD2) U8.Y4(VDD3)
+V2P8A_EMMC: C141.1 C142.1 R155.1 R574.1 U8.M6(VDDF1) U8.N5(VDDF2) U8.T10(VDDF3) U8.U9(VDDF4)
+V3.3A: C22.1 C113.1 C173.1 C174.1 C238.1 C257.1 C265.1 C332.1 C333.1 C405.1 C411.1 C414.1 C419.1 C421.1 CP7.1 CP8.1 D8.P D27.P D30.P FB37.1 FB38.1 L2.2 LED2.1(P) Q21.5(D1) Q21.6(D2) Q21.7(D3) Q21.8(D4) R113.2 R118.2 R123.2 R143.2 R144.2 R172.2 R183.2 R188.1 R295.2 R296.2 R374.2 R375.2 R406.1 R410.2 R413.1 R554.2 R587.1 R592.2 R3105.1 R3109.1 U6.11(VCCB) U7.5(VCC) U11.32(PVINSWA1) U21.5(VIN) U27.5(VCC) U28.5(VIN) U29.6(VCCB) U30.11(VCCB) U32.11(VCCB) U44.5(VIN)
+V3.3A_KBC: C415.2 C416.2 D12.P D29.N D30.N D31.N FB15.1 R385.1 R388.1 R389.2 R392.1 R394.1 R396.1 R399.1 R405.1 R408.1 R445.2 R456.1 R457.2 R591.1 R828.2 U31.26(VSTBY6) U31.50(VSTBY5) U31.92(VSTBY4) U31.114(VSTBY3) U31.121(VSTBY2) U31.127(VSTBY1(PLL))
+V3.3A_LDO: C184.2 U11.54(LDO3P3)
+V3.3A_PRIME: C101.2 C102.2 C104.2 C266.2 C267.1 R133.2 R155.2 R231.2 U1.B22(USB_V3P3A_G31) U1.C23(USB_V3P3A_G32) U1.D4(RTC_V3P3A_G51) U1.E3(RTC_V3P3A_G52) U44.1(VOUT)
+V3.3A_RTC: C98.2 C488.2 D26.N D27.N R79.2 R83.2 R387.1 U1.B6(RTC_V3P3RTC_G51) U1.C5(RTC_V3P3RTC_G52)
+V3.3A_SW: C243.2 R140.2 R207.2 R231.1 R558.2 U11.31(SWA1)
+V3.3A_WIFI: C400.1 C401.2 C402.2 C409.2 C410.1 C799.2 C800.2 C801.2 CN26.2(3.3V_2) CN26.4(3.3V_4) CN26.72(3.3V_72) CN26.74(3.3V_74) Q41.1(G) R374.1 R789.1 U28.1(VOUT)
+V3.3AVCC: C417.1 FB15.2 U31.74(AVCC)
+V3.3S: C15.1 C114.2 C115.2 C258.2 C259.1 C374.1 C395.2 C426.2 CN1.199(VDDSPD) CN11.1 CN11.2 CN11.14 CN11.15 CN11.18 FB4.1 FB6.2 FB12.2 FB19.2 FB25.2 Q21.1(S1) Q21.2(S2) Q21.3(S3) R69.1 R70.1 R126.2 R146.1 R147.2 R247.2 R251.1 R253.1 R294.1 R305.2 R350.1 R351.1 R353.1 R364.1 R365.1 R536.1 R537.1 R539.1 R540.1 R574.2 R584.1 R586.1 R590.2 U5.8(VCCB) U26.5(VCC) U33.5(VCC) U42.5(VCC)
+V3.3S_AUDIO: C367.2 C368.2 FB12.1 FB13.1 R346.1 U25.36(CPVDD)
+V3.3S_MSATA: C313.2 C314.2 C315.2 C316.2 CN9.2(3.3V_2) CN9.4(3.3V_4) CN9.12(3.3V_12) CN9.14(3.3V_14) CN9.16(3.3V_16) CN9.18(3.3V_18) CN9.70(3.3V_70) CN9.72(3.3V_72) CN9.74(3.3V_74) FB25.1
+V5_AVDD: C369.2 C370.1 D43.N FB8.1 R349.2 R355.2 U25.26(AVDD1)
+V5_PVDD: C380.2 C381.1 C382.2 C383.1 FB9.1 U25.41(PVDD1) U25.46(PVDD2)
+V5A: C11.2 C167.1 C168.1 C180.1 C214.1 C218.1 C236.1 C237.1 C253.1 C436.1 C437.1 C444.1 C449.1 C454.1 C829.1 C830.1 C831.1 C2836.1 CP5.1 CP6.1 D4.1(X1) F2.1 F3.1 F4.1 F5.1 L1.1 Q18.5(D1) Q18.6(D2) Q18.7(D3) Q18.8(D4) R171.2 R174.1 R177.1 R180.1 R475.1 R482.1 R487.1 R492.1 U3.4(VBIAS) U10.14(VO1) U11.11(PVIN3) U11.21(PVIN5) U11.24(PVIN4) U11.57(V5ANA) U35.5(VIN) U38.5(VIN) U39.5(VIN) U40.5(VIN) U53.10(VCNTL) U2525.10(VCNTL)
+V5A_LDO: C182.2 C212.2 C215.1 U11.8(DRV5V_2_EC) U11.38(DRV5V_1_6) U11.56(LDO5P0)
+V5S: C254.2 C255.1 C360.1 C361.1 D43.P FB8.2 FB9.2 FB24.2 FB27.2 Q18.1(S1) Q18.2(S2) Q18.3(S3) R2.1 R223.1 R225.1 R246.1 R418.1 R419.1
+V5S_HDD: C261.1 C264.1 C319.2 C320.2 CN3.P8 CN3.P9 FB27.1 R748.1
+V15A: C179.1 D5.2(X2) R215.1 R216.1 R220.1 R221.1
+VCCCFIOAZA: C112.1 R137.2 R138.2 U1.AF4(UNCORE_V1P8A_G31) U1.AH4(UNCORE_V1P8A_G32)
+VCCDPYCSIAON_1P24: C81.2 R130.2 R136.2 U1.P40(MIPI_V1P2A_G31) U1.T40(MIPI_V1P2A_G32)
+VCCPADHSICAON_1P24: R131.2 R139.2 U1.M41(USBHSIC_V1P2A_G3)
+VCCPADSSICAON_1P24: R132.2 R142.2 U1.P41(USBSSIC_V1P2A_G3)
+VDDI_EMMC: C143.1 U8.K2(VDDI)
AGND: B1.2(S) C363.2 C365.1 C369.1 C370.2 C371.1 C372.2 C376.1 C393.2 C394.2 C396.2 C397.2 C398.2 C399.2 CN7.1 CN7.E1 CN7.E2 FB14.2 J2.2 J2.5 J3.2 J3.5 Q36.2(S) R338.2 R356.2 R357.2 U25.25(AVSS1) U25.38(AVSS2)
AVDD2: C371.2 C372.1 FB10.1 FB11.1 U25.40(AVDD2)
AVDD33: C702.2 C703.1 FB20.1 U95.4(AVDD33)
AVDD33_REG: C335.2 C336.1 R299.1 U22.34(VDDREG) U22.35(VDDREGA)
GND: C1.1 C2.2 C7.2 C8.1 C9.1 C10.1 C11.1 C12.1 C13.1 C14.2 C15.2 C16.1 C17.1 C18.2 C19.2 C20.1 C21.2 C22.2 C23.1 C24.1 C25.1 C26.1 C27.1 C28.1 C29.2 C30.2 C31.2 C32.2 C33.2 C34.2 C35.2 C36.2 C37.2 C38.2 C39.2 C40.2 C41.2 C42.1 C43.1 C44.1 C45.1 C46.1 C47.1 C48.1 C49.2 C50.2 C51.2 C52.1 C53.1 C54.2 C55.2 C56.1 C57.1 C58.1 C59.1 C60.1 C61.1 C62.1 C63.1 C64.1 C65.1 C66.1 C67.1 C68.1 C69.1 C70.1 C71.1 C72.1 C73.2 C74.2 C75.2 C76.2 C77.2 C78.1 C79.1 C80.2 C81.1 C82.1 C83.1 C84.1 C85.1 C86.1 C87.2 C88.1 C89.1 C90.1 C91.2 C92.2 C93.2 C94.2 C95.1 C96.1 C97.1 C98.1 C99.1 C100.1 C101.1 C102.1 C103.1 C104.1 C105.2 C106.1 C107.1 C108.1 C109.1 C110.1 C111.1 C112.2 C113.2 C114.1 C115.1 C116.1 C117.1 C118.2 C119.1 C120.1 C121.1 C122.1 C123.1 C124.1 C125.1 C126.1 C127.1 C128.1 C129.1 C130.1 C131.1 C132.1 C133.1 C134.1 C135.1 C136.1 C137.1 C138.1 C139.1 C140.1 C141.2 C142.2 C143.2 C144.2 C145.2 C146.1 C147.1 C148.1 C149.1 C150.1 C151.1 C152.1 C153.1 C154.1 C155.1 C156.2 C157.2 C158.2 C159.2 C160.1 C161.2 C163.1 C164.2 C167.2 C168.2 C173.2 C174.2 C175.1 C176.1 C179.2 C180.2 C181.2 C185.2 C186.2 C188.2 C189.2 C190.2 C195.2 C197.2 C198.2 C199.2 C200.2 C202.2 C203.2 C204.2 C205.2 C206.2 C207.2 C208.2 C209.2 C210.2 C212.1 C214.2 C215.2 C216.2 C217.2 C218.2 C219.2 C220.2 C222.2 C224.2 C225.2 C226.2 C227.2 C228.2 C229.2 C230.2 C231.2 C232.2 C236.2 C237.2 C238.2 C239.2 C240.2 C241.2 C242.2 C244.1 C245.1 C246.1 C247.1 C249.2 C250.2 C251.2 C252.2 C253.2 C254.1 C255.2 C256.1 C257.2 C258.1 C259.2 C260.1 C261.2 C264.2 C265.2 C266.1 C267.2 C268.1 C283.1 C284.2 C286.1 C288.2 C295.1 C297.2 C298.2 C300.1 C301.1 C302.2 C304.1 C305.1 C306.1 C307.1 C308.2 C309.2 C310.1 C311.1 C313.1 C314.1 C315.1 C316.1 C319.1 C320.1 C323.2 C324.2 C325.2 C326.2 C327.2 C328.2 C329.2 C330.2 C331.2 C332.2 C333.2 C334.1 C335.1 C336.2 C337.1 C338.2 C339.2 C340.2 C341.2 C342.2 C343.2 C344.2 C345.2 C348.1 C349.2 C350.1 C351.1 C356.2 C357.2 C358.1 C359.1 C360.2 C361.2 C362.1 C364.2 C366.2 C367.1 C368.1 C374.2 C380.1 C381.2 C382.1 C383.2 C385.1 C386.2 C387.1 C388.1 C389.1 C390.1 C391.1 C392.1 C395.1 C400.2 C401.1 C402.1 C405.2 C409.1 C410.2 C411.2 C412.1 C413.2 C414.2 C415.1 C416.1 C417.2 C418.2 C419.2 C420.2 C421.2 C422.1 C423.2 C424.2 C425.2 C426.1 C427.2 C428.2 C435.2 C436.2 C437.2 C438.2 C439.2 C440.2 C441.2 C444.2 C445.2 C446.2 C447.2 C448.2 C449.2 C450.2 C451.2 C452.2 C453.2 C454.2 C455.2 C456.2 C457.2 C458.2 C459.1 C460.1 C461.1 C462.2 C464.1 C466.2 C468.1 C488.1 C527.2 C557.2 C560.1 C561.1 C562.1 C565.1 C566.1 C603.2 C607.1 C691.2 C700.2 C701.2 C702.1 C703.2 C704.2 C705.2 C706.1 C707.2 C708.2 C710.1 C727.1 C799.1 C800.1 C801.1 C822.2 C823.1 C826.2 C827.2 C828.2 C829.2 C830.2 C831.2 C942.1 C992.2 C2833.2 C2834.2 C2835.2 C2836.2 C2837.2 C2838.2 CN1.2(VSS1) CN1.3(VSS2) CN1.8(VSS3) CN1.9(VSS4) CN1.13(VSS5) CN1.14(VSS6) CN1.19(VSS7) CN1.20(VSS8) CN1.25(VSS9) CN1.26(VSS10) CN1.31(VSS11) CN1.32(VSS12) CN1.37(VSS13) CN1.38(VSS14) CN1.43(VSS15) CN1.44(VSS16) CN1.48(VSS17) CN1.49(VSS18) CN1.54(VSS19) CN1.55(VSS20) CN1.60(VSS21) CN1.61(VSS22) CN1.65(VSS23) CN1.66(VSS24) CN1.71(VSS25) CN1.72(VSS26) CN1.127(VSS27) CN1.128(VSS28) CN1.133(VSS29) CN1.134(VSS30) CN1.138(VSS31) CN1.139(VSS32) CN1.144(VSS33) CN1.145(VSS34) CN1.150(VSS35) CN1.151(VSS36) CN1.155(VSS37) CN1.156(VSS38) CN1.161(VSS39) CN1.162(VSS40) CN1.167(VSS41) CN1.168(VSS42) CN1.172(VSS43) CN1.173(VSS44) CN1.178(VSS45) CN1.179(VSS46) CN1.184(VSS47) CN1.185(VSS48) CN1.189(VSS49) CN1.190(VSS50) CN1.195(VSS51) CN1.196(VSS52) CN1.E1 CN1.E2 CN3.E1 CN3.E2 CN3.P4 CN3.P5 CN3.P6 CN3.P10 CN3.P12 CN3.S1 CN3.S4 CN3.S7 CN9.1(GND_1) CN9.3(GND_3) CN9.9(GND_9) CN9.15(GND_15) CN9.21(GND_21) CN9.27(GND_27) CN9.33(GND_33) CN9.39(GND_39) CN9.45(GND_45) CN9.51(GND_51) CN9.57(GND_57) CN9.71(GND_71) CN9.73(GND_73) CN9.75(GND_75) CN9.E1 CN9.E2 CN10.E1 CN10.E2 CN11.3 CN11.16 CN11.17 CN11.19 CN11.E1 CN11.E2 CN12.E1 CN12.E2 CN18.4(GND1) CN18.7(GND_DRAIN) CN18.E1(GND2) CN18.E2(GND3) CN18.E3(GND4) CN18.E4(GND5) CN19.4(GND1) CN19.E1(GND2) CN19.E2(GND3) CN20.4(GND1) CN20.E1(GND2) CN20.E2(GND3) CN21.C CN23.3(VSS1) CN23.6(VSS2) CN23.E1 CN23.E2 CN23.E3 CN23.E4 CN24.2(1-) CN25.4 CN25.E1 CN25.E2 CN26.1(GND_1) CN26.7(GND_7) CN26.18(GND_18) CN26.23(GND_23) CN26.24(GND_24) CN26.29(GND_29) CN26.33(GND_33) CN26.36(GND_36) CN26.39(GND_39) CN26.45(GND_45) CN26.51(GND_51) CN26.57(GND_57) CN26.63(GND_63) CN26.69(GND_69) CN26.75(GND_75) CN26.E1 CN26.E2 CN35.1 CN35.4 CN35.7 CN35.12 CN35.19 CN35.20 CN35.21 CN35.22 CN35.25 CN35.28 CN35.31 CN35.34 CN35.37 CN35.40 CN35.E1 CN35.E2 CP1.2 CP3.2 CP4.2 CP5.2 CP6.2 CP7.2 CP8.2 CP9.2 CP10.2 CP11.2 CP12.2 CP13.2 CP14.2 CP15.2 CP16.2 CP17.2 CP18.2 CP19.2 CP20.2 CP21.2 CP50.2 D2.P D3.P D13.P D14.P D17.P D18.P D19.P D20.P D21.P D2512.P D2513.P FB7.1 FB14.1 J4.4(GND1) J4.7(GND_DRAIN) J4.E1(GND2) J4.E2(GND3) J4.E3(GND4) J4.E4(GND5) J5.E1 J5.E2 MH1.1 MH2.1 MH3.1 MH4.1 MH5.1 MH6.1 MH7.1 MH8.1 MH9.1 MH10.1 MH11.1 MH12.1 MH13.1 Q1.2(GND) Q4.2(S) Q5.2(S) Q8.2(S) Q9.3(S2) Q9.4(S3) Q9.5(S4) Q10.4 Q13.4 Q14.3(S2) Q14.4(S3) Q14.5(S4) Q15.3(S2) Q15.4(S3) Q15.5(S4) Q16.2(GND) Q19.2(S) Q20.2(S) Q22.2(S) Q23.2(S) Q30.2(S) Q31.2(S) Q37.2(S) Q38.2(S) Q39.2(S) Q40.2(S) Q42.2(S) Q43.2(S) Q45.2(S) Q46.2(S) Q48.2(S) Q49.2(S) Q50.2(S) Q51.2(S) R1.2 R16.2 R19.1 R20.2 R21.2 R46.1 R47.1 R49.1 R56.2 R57.2 R59.2 R60.1 R74.2 R75.2 R76.2 R77.1 R78.1 R80.1 R82.2 R84.2 R86.2 R91.2 R92.2 R93.1 R100.1 R121.1 R124.1 R129.2 R130.1 R131.1 R132.1 R135.2 R145.1 R150.2 R151.2 R152.1 R154.1 R170.1 R176.1 R178.2 R179.2 R181.2 R182.1 R184.2 R209.1 R218.1 R224.1 R230.1 R232.1 R233.1 R255.2 R258.2 R266.1 R267.1 R275.1 R297.2 R298.1 R300.1 R301.1 R303.2 R307.2 R313.2 R341.1 R366.2 R380.1 R443.2 R448.2 R452.2 R453.1 R458.1 R462.2 R463.2 R464.1 R474.1 R481.1 R486.1 R491.1 R495.1 R501.1 R531.2 R538.2 R544.2 R553.1 R555.1 R564.2 R567.1 R582.1 R583.1 R585.1 R593.2 R594.1 R595.1 R596.2 R597.1 R599.2 R600.2 R601.2 R636.1 R638.1 R648.2 R663.1 R681.1 R707.1 R754.2 R755.2 R756.1 R800.2 R802.1 R827.1 R837.2 R838.2 R839.1 R842.2 R883.1 R958.1 R2984.1 R3100.1 R3106.2 R3113.1 SW1.2 SW1.E1 SW1.E2 SW2.2 SW2.4 U1.A5(VSS1) U1.A7(VSS3) U1.A11(VSS1) U1.A15(VSS2) U1.A19(VSS3) U1.A23(VSS4) U1.A31(VSS5) U1.A39(VSS6) U1.A43(VSS7) U1.A47(VSS8) U1.AA16(VSS9) U1.AA27(VSS10) U1.AA38(VSS11) U1.AA53(VSS12) U1.AB4(VSS17) U1.AB6(VSS21) U1.AB10(VSS13) U1.AB12(VSS14) U1.AB13(VSS15) U1.AB14(VSS16) U1.AB42(VSS18) U1.AB47(VSS19) U1.AB50(VSS20) U1.AC16(VSS22) U1.AC29(VSS23) U1.AC33(VSS24) U1.AC35(VSS25) U1.AC38(VSS26) U1.AD4(VSS31) U1.AD21(VSS27) U1.AD30(VSS28) U1.AD32(VSS29) U1.AD36(VSS30) U1.AD44(VSS32) U1.AE1(VSS33) U1.AE6(VSS45) U1.AE8(VSS46) U1.AE9(VSS47) U1.AE11(VSS34) U1.AE12(VSS35) U1.AE14(VSS36) U1.AE40(VSS37) U1.AE42(VSS38) U1.AE43(VSS39) U1.AE45(VSS40) U1.AE46(VSS41) U1.AE48(VSS42) U1.AE50(VSS43) U1.AE53(VSS44) U1.AF10(VSS48) U1.AF24(VSS1) U1.AF25(VSS49) U1.AF27(CORE_VSS1_SENSE) U1.AF32(VSS50) U1.AF38(VSS51) U1.AF47(VSS52) U1.AG25(VSS53) U1.AH9(VSS62) U1.AH10(VSS54) U1.AH12(VSS55) U1.AH13(VSS56) U1.AH14(VSS57) U1.AH41(VSS58) U1.AH42(VSS59) U1.AH44(VSS60) U1.AH47(VSS61) U1.AJ1(VSS63) U1.AJ3(VSS66) U1.AJ16(VSS64) U1.AJ18(VSS1) U1.AJ25(VSS65) U1.AJ32(CORE_VSS0_SENSE) U1.AJ51(VSS67) U1.AJ53(VSS68) U1.AK4(VSS74) U1.AK7(VSS80) U1.AK16(VSS69) U1.AK22(VSS2) U1.AK25(VSS70) U1.AK27(VSS71) U1.AK29(VSS3) U1.AK32(VSS72) U1.AK38(VSS73) U1.AK40(VSS75) U1.AK44(VSS76) U1.AK45(VSS77) U1.AK47(VSS78) U1.AK50(VSS79) U1.AM4(VSS87) U1.AM13(VSS4) U1.AM16(VSS81) U1.AM24(VSS82) U1.AM27(VSS83) U1.AM30(VSS84) U1.AM35(VSS85) U1.AM38(VSS86) U1.AM42(VSS88) U1.AM50(VSS89) U1.AN1(VSS90) U1.AN3(VSS98) U1.AN5(VSS15) U1.AN6(VSS18) U1.AN8(VSS19) U1.AN9(VSS20) U1.AN11(VSS91) U1.AN12(VSS92) U1.AN14(VSS93) U1.AN16(VSS94) U1.AN21(VSS5) U1.AN24(VSS95) U1.AN25(VSS96) U1.AN29(VSS97) U1.AN30(VSS6) U1.AN33(VSS2) U1.AN38(VSS7) U1.AN40(VSS8) U1.AN42(VSS9) U1.AN43(VSS10) U1.AN45(VSS11) U1.AN46(VSS12) U1.AN48(VSS13) U1.AN49(VSS14) U1.AN51(VSS16) U1.AN53(VSS17) U1.AP4(VSS21) U1.AP9(VSS24) U1.AP45(VSS22) U1.AP50(VSS23) U1.AT3(VSS28) U1.AT9(VSS33) U1.AT18(VSS25) U1.AT19(VSS26) U1.AT27(VSS27) U1.AT35(VSS29) U1.AT36(VSS30) U1.AT45(VSS31) U1.AT51(VSS32) U1.AU1(VSS34) U1.AU3(VSS35) U1.AU51(VSS36) U1.AU53(VSS37) U1.AV14(VSS38) U1.AV19(VSS39) U1.AV24(VSS40) U1.AV27(VSS41) U1.AV30(VSS42) U1.AV35(VSS43) U1.AV40(VSS44) U1.AW13(VSS3) U1.AW19(VSS45) U1.AW27(VSS46) U1.AW35(VSS47) U1.AW41(VSS4) U1.AY3(VSS53) U1.AY7(VSS60) U1.AY9(VSS61) U1.AY20(VSS48) U1.AY22(VSS49) U1.AY24(VSS50) U1.AY26(VSS51) U1.AY28(VSS52) U1.AY30(VSS54) U1.AY32(VSS55) U1.AY34(VSS56) U1.AY45(VSS57) U1.AY47(VSS58) U1.AY51(VSS59) U1.B2(VSS4) U1.B28(VSS62) U1.B36(VSS63) U1.BA19(VSS64) U1.BA24(VSS65) U1.BA27(VSS66) U1.BA30(VSS67) U1.BA35(VSS68) U1.BB4(VSS6) U1.BB19(VSS69) U1.BB27(VSS70) U1.BB35(VSS71) U1.BB50(VSS7) U1.BC10(VSS72) U1.BC14(VSS73) U1.BC16(VSS74) U1.BC26(VSS75) U1.BC28(VSS76) U1.BC38(VSS77) U1.BC40(VSS78) U1.BC44(VSS79) U1.BD1(VSS80) U1.BD19(VSS81) U1.BD27(VSS82) U1.BD35(VSS83) U1.BD53(VSS84) U1.BE19(VSS85) U1.BE35(VSS86) U1.BF4(VSS8) U1.BF12(VSS87) U1.BF22(VSS88) U1.BF26(VSS89) U1.BF27(VSS90) U1.BF28(VSS91) U1.BF32(VSS92) U1.BF42(VSS93) U1.BF50(VSS9) U1.BG1(VSS10) U1.BG5(VSS11) U1.BG7(VSS102) U1.BG14(VSS94) U1.BG16(VSS95) U1.BG18(VSS96) U1.BG19(VSS97) U1.BG20(VSS98) U1.BG24(VSS99) U1.BG27(VSS100) U1.BG30(VSS101) U1.BG34(VSS5) U1.BG35(VSS6) U1.BG36(VSS7) U1.BG38(VSS8) U1.BG40(VSS9) U1.BG47(VSS11) U1.BG49(VSS10) U1.BG53(VSS12) U1.BH1(VSS13) U1.BH2(VSS14) U1.BJ7(VSS22) U1.BJ11(VSS12) U1.BJ15(VSS13) U1.BJ19(VSS14) U1.BJ23(VSS15) U1.BJ27(VSS16) U1.BJ31(VSS17) U1.BJ35(VSS18) U1.BJ39(VSS19) U1.BJ43(VSS20) U1.BJ47(VSS21) U1.C1(VSS17) U1.C3(VSS25) U1.C20(VSS103) U1.C22(VSS23) U1.C28(VSS24) U1.C30(VSS26) U1.C36(VSS27) U1.C39(VSS28) U1.C47(VSS29) U1.D10(VSS30) U1.D16(VSS31) U1.D24(VSS32) U1.D27(VSS33) U1.D32(VSS34) U1.D38(VSS35) U1.D40(VSS36) U1.D42(VSS37) U1.E19(VSS38) U1.E35(VSS39) U1.E46(VSS40) U1.E51(VSS41) U1.F1(VSS18) U1.F5(VSS47) U1.F19(VSS42) U1.F24(VSS43) U1.F27(VSS44) U1.F32(VSS45) U1.F35(VSS46) U1.G12(VSS48) U1.G14(VSS49) U1.G22(VSS50) U1.G26(VSS51) U1.G28(VSS52) U1.G30(VSS53) U1.H8(VSS57) U1.H19(VSS54) U1.H27(VSS55) U1.H35(VSS56) U1.J18(VSS58) U1.J19(VSS59) U1.J22(VSS60) U1.J27(VSS61) U1.J30(VSS62) U1.J35(VSS63) U1.J38(VSS64) U1.J42(VSS65) U1.J53(VSS66) U1.K4(VSS76) U1.K12(VSS67) U1.K14(VSS68) U1.K16(VSS69) U1.K22(VSS70) U1.K24(VSS71) U1.K30(VSS72) U1.K32(VSS73) U1.K34(VSS74) U1.K36(VSS75) U1.K45(VSS77) U1.K50(VSS78) U1.L1(VSS79) U1.L19(VSS80) U1.L27(VSS81) U1.L35(VSS82) U1.L41(VSS19) U1.M9(VSS90) U1.M14(VSS83) U1.M19(VSS84) U1.M24(VSSA) U1.M27(VSS85) U1.M35(VSS86) U1.M40(VSS87) U1.M45(VSS88) U1.M50(VSS89) U1.N22(VSS91) U1.N24(VSS92) U1.N32(VSS93) U1.N51(VSS94) U1.N53(VSS95) U1.P4(VSS22) U1.P10(VSS99) U1.P19(VSS96) U1.P22(VSS97) U1.P27(VSS98) U1.P32(VSS99) U1.P35(VSS20) U1.P36(VSS21) U1.P42(VSS23) U1.R1(VSS24) U1.T9(VSS26) U1.T14(VSS25) U1.T47(VSS100) U1.U5(VSS45) U1.U6(VSS47) U1.U8(VSS48) U1.U9(VSS49) U1.U11(VSS27) U1.U12(VSS28) U1.U14(VSS29) U1.U18(VSS30) U1.U21(VSS31) U1.U25(VSS100) U1.U29(VSS32) U1.U30(VSS33) U1.U32(VSS34) U1.U33(VSS35) U1.U36(VSS36) U1.U38(VSS37) U1.U40(VSS38) U1.U42(VSS39) U1.U43(VSS40) U1.U45(VSS41) U1.U46(VSS42) U1.U48(VSS43) U1.U49(VSS44) U1.U53(VSS46) U1.V16(VSS50) U1.V21(VSS51) U1.V25(VSS101) U1.V32(VSS52) U1.V38(VSS53) U1.V41(VSS54) U1.V42(VSS55) U1.V44(VSS56) U1.W1(VSS57) U1.Y4(VSS66) U1.Y9(VSS70) U1.Y10(VSS58) U1.Y14(VSS59) U1.Y16(VSS60) U1.Y19(VSS61) U1.Y21(VSS62) U1.Y22(VSS63) U1.Y24(VSS102) U1.Y29(VSS64) U1.Y38(VSS65) U1.Y40(VSS67) U1.Y45(VSS68) U1.Y50(VSS69) U2.4(VSS) U3.5(GND) U3.E1 U4.4(GND) U4.E1 U5.4(GND) U6.6(GND) U7.3(GND) U8.AA4(VSS8) U8.AA6(VSS3) U8.K4(VSS6) U8.M7(VSS2) U8.P5(VSS4) U8.R10(VSS9) U8.U8(VSS1) U8.Y2(VSS7) U8.Y5(VSS5) U9.15(GND) U10.E1 U11.E1 U15.2(GND) U16.3(GND) U16.17(GNDX) U16.18(GNDX_1) U16.28(GND1) U16.E1 U17.1(A0/E0) U17.2(A1/E1) U17.3(A2/E2) U17.4(GND) U18.1(A0/E0) U18.2(A1/E1) U18.3(A2/E2) U18.4(GND) U21.2(GND) U22.24(GND) U22.E1(EPAD) U25.4(DVSS) U25.E1 U26.3(GND) U27.3(GND) U28.2(GND) U29.2(GND) U30.6(GND) U31.1(VSS1) U31.27(VSS2) U31.49(VSS3) U31.75(AVSS) U31.91(VSS4) U32.6(GND) U33.3(GND) U34.4(GND) U35.2(GND) U36.3(GND) U37.3(GND) U38.2(GND) U39.2(GND) U40.2(GND) U41.3(GND) U41.E1 U42.3(GND) U44.2(GND) U46.2(GND) U53.E1 U95.E1 U2523.3(GND) U2524.3(GND) U2525.E1 X1.2 X1.4 X2.2 X2.3 X4.2 X4.4 X5.2 X5.4 X6.2 X6.3
GND_EARTH: C352.2 C353.1 C354.1 C355.2 C356.1 C357.1 CN6.E1 CN6.E2 FB7.2
PGNDSNS1: R837.1 U11.36(PGNDSNS1)
PGNDSNS6: R838.1 U11.40(PGNDSNS6)
V1P24A_PWRGD: R559.2 R3105.2 U53.5(POK)
VBAT: R385.2 R387.2 U31.3(VBAT)
VCC0_SENSEP_R: R101.1 U1.AG32(CORE_VCC0_SENSE)
VCC1_SENSEP_R: R103.1 U1.AD29(CORE_VCC1_SENSE)
VCC1_USB3.0: C438.1 C439.1 C440.1 CP21.1 F2.2 J4.1(VBUS) R472.2 U35.1(VOUT)
VCC2_USB3.0: C445.1 C446.1 C447.1 CN18.1(VBUS) CP20.1 F3.2 R479.2 U38.1(VOUT)
VCC_8625: C308.1 FB6.1 FB38.2 R269.2 R270.2 R271.2 R276.1 R277.1 U16.13(VDDIOX) U16.14(VDDIOX_1) U17.8(VCC) U18.8(VCC)
VCC_LX: C223.1 L5.1 Q15.7(S1/D2) R579.2 U11.34(SW1)
VCC_SENSEP: R101.2 R103.2 R563.2
VCC_USB2: C450.1 C451.1 C452.1 CN19.1(VBUS) F4.2 R484.2 U39.1(VOUT)
VCC_USB3: C455.1 C456.1 C457.1 CN20.1(VBUS) F5.2 R490.2 U40.1(VOUT)
VDD10: C337.2 C338.1 C339.1 C340.1 C341.1 C342.1 C343.1 C344.1 C345.1 L10.2 R309.2 U22.3(AVDD10) U22.6(AVDD10(NC)) U22.9(AVDD10A(NC)) U22.13(DVDD10) U22.29(DVDD10A) U22.41(DVDD10(NC)) U22.45(AVDD10A)
VDD12: C309.1 C310.2 C311.2 FB5.2 L9.1 U16.19(VDD12)
VDD18: C706.2 U95.18(VDD18)
VDD33: C325.1 C326.1 C327.1 C328.1 C329.1 C330.1 C331.1 Q35.1(G) R294.2 R295.1 R299.2 R302.1 R317.1 U21.1(VOUT) U22.12(AVDD33(NC)) U22.27(DVDD33) U22.39(DVDD3) U22.42(AVDD33) U22.47(AVDD33A) U22.48(AVDD33B)
VDDIO_8625: C295.2 C304.2 FB4.2 FB37.2 R262.2 R263.2 R272.2 R273.2 R274.2 U16.38(VDDIO) U16.50(VDDIO_1)
VDDQ_LX: C213.1 L3.1 Q13.5 Q13.6 Q13.7 R581.2 U11.42(SW6)
VDDRX: C305.2 C306.2 C307.2 FB5.1 U16.6(VDDRX)
VIN_LCD: C302.1 C603.1 C607.2 F9.1 L32.1 R3089.2 R3090.2 U41.13(VIN)
3.3A_PRIME_EN: U31.97(HSCK/GPH4/ID4)
5A_ONOFF: R185.1 R186.2 R403.2 R444.2 R600.1 R601.1 U10.6(EN2) U10.20(EN1)
8625_PD#: C301.2 R263.1 U16.10(PD#)
8625_PWMO: R528.2 U16.12(PWMO)
8625_RST#: C300.2 R262.1 U16.9(RST#)
+V_ADP_IN: C459.2 C460.2 C462.1 C464.2 C465.2 CP14.1 F6.2 FB16.1 FB17.1 Q44.1(S1) Q44.2(S2) Q44.3(S3) R494.2 R496.2 R499.2
+V_DC: C157.1 C158.1 C159.1 C160.2 C161.1 C163.2 C164.1 C176.2 C185.1 C186.1 C188.1 C189.1 C190.1 C195.1 C197.1 C198.1 C199.1 C200.1 C216.1 C217.1 C219.1 C220.1 C222.1 C466.1 C468.2 CP15.1 CP16.1 CP17.1 CP18.1 CP19.1 F6.1 F9.2 Q9.2(D1) Q10.1 Q10.2 Q13.1 Q13.2 Q14.2(D1) Q15.2(D1) Q44.5(D1) Q44.6(D2) Q44.7(D3) Q44.8(D4) R194.1 R497.2 U10.12(VIN)
+V_LED: C297.1 C298.1 C2833.1 CN22.1 CP50.1 D38.N D42.N J5.3 J5.4 R645.1 R3096.1
+VCORE: C32.1 C33.1 C34.1 C35.1 C36.1 C37.1 C38.1 C39.1 C40.1 C41.1 C224.1 C225.1 C226.1 C227.1 C228.1 CP12.1 CP13.1 L5.2 R823.2 U1.AF29(CORE_VCC1_S0IX1) U1.AF30(CORE_VCC1_S0IX2) U1.AF36(CORE_VCC1_S0IX3) U1.AG27(CORE_VCC1_S0IX4) U1.AG29(CORE_VCC1_S0IX5) U1.AG30(CORE_VCC1_S0IX6) U1.AG33(CORE_VCC1_S0IX7) U1.AG35(CORE_VCC1_S0IX8) U1.AG36(CORE_VCC1_S0IX9) U1.AG38(CORE_VCC1_S0IX10) U1.AJ27(CORE_VCC1_S0IX11) U1.AJ29(CORE_VCC1_S0IX12) U1.AJ30(CORE_VCC1_S0IX13) U1.AJ33(CORE_VCC1_S0IX14) U1.AJ36(CORE_VCC1_S0IX15) U1.AJ38(CORE_VCC1_S0IX16)
+VEC_LDO: C221.2 D31.P R389.1 U11.9(ECLDOUT)
+VGG: C49.1 C50.1 C51.1 C203.1 C206.1 C207.1 C208.1 C209.1 CP1.1 CP10.1 CP11.1 L4.1 R825.2 U1.AD16(DDI_VGG_S0IX1) U1.AD18(DDI_VGG_S0IX2) U1.AD19(DDI_VGG_S0IX3) U1.AF16(DDI_VGG_S0IX4) U1.AF18(DDI_VGG_S0IX5) U1.AF19(DDI_VGG_S0IX6) U1.AF21(DDI_VGG_S0IX7) U1.AF22(DDI_VGG_S0IX8) U1.AG16(DDI_VGG_S0IX9) U1.AG18(DDI_VGG_S0IX10) U1.AG19(DDI_VGG_S0IX11) U1.AG21(DDI_VGG_S0IX12) U1.AG22(DDI_VGG_S0IX13) U1.AG24(DDI_VGG_S0IX14) U1.AJ19(DDI_VGG_S0IX15) U1.AJ21(DDI_VGG_S0IX16) U1.AJ22(DDI_VGG_S0IX17) U1.AJ24(DDI_VGG_S0IX18) U1.AK24(DDI_VGG_S0IX19)
+VNN: C25.2 C26.2 C27.2 C28.2 C29.1 C30.1 C31.1 C229.1 C230.1 C231.1 C232.1 C826.1 C827.1 C828.1 L6.1 R821.2 U1.AA18(UNCORE_VNN_S41) U1.AA19(UNCORE_VNN_S42) U1.AA21(UNCORE_VNN_S43) U1.AA22(UNCORE_VNN_S44) U1.AA24(UNCORE_VNN_S45) U1.AA25(UNCORE_VNN_S46) U1.AC18(UNCORE_VNN_S47) U1.AC19(UNCORE_VNN_S48) U1.AC21(UNCORE_VNN_S49) U1.AC22(UNCORE_VNN_S410) U1.AC24(UNCORE_VNN_S411) U1.AC25(UNCORE_VNN_S412) U1.AD25(UNCORE_VNN_S413) U1.AD27(UNCORE_VNN_S414)
+VSDIO: C99.2 C100.2 R140.1 R141.1 U1.E1(SDIO_V3P3A_V1P8A_G31) U1.E2(SDIO_V3P3A_V1P8A_G32)
+VSM: C80.1 C82.2 C87.1 C88.2 C91.1 C92.1 C93.1 C94.1 C121.2 C122.2 C123.2 C124.2 C125.2 C126.2 C127.2 C128.2 C133.2 C134.2 C135.2 C136.2 C137.2 C138.2 C139.2 C140.2 C202.1 C204.1 C205.1 C210.1 CN1.75(VDD1) CN1.76(VDD2) CN1.81(VDD3) CN1.82(VDD4) CN1.87(VDD5) CN1.88(VDD6) CN1.93(VDD7) CN1.94(VDD8) CN1.99(VDD9) CN1.100(VDD10) CN1.105(VDD11) CN1.106(VDD12) CN1.111(VDD13) CN1.112(VDD14) CN1.117(VDD15) CN1.118(VDD16) CN1.123(VDD17) CN1.124(VDD18) CP4.1 CP9.1 L3.2 R9.1 R148.2 R153.2 R214.1 U1.AM18(DDR_VDDQ_G_S41) U1.AM25(DDR_VDDQ_G_S42) U1.AM36(DDR_VDDQ_G_S43) U1.AN18(DDR_VDDQ_G_S44) U1.AN19(DDR_VDDQ_G_S45) U1.AN27(DDRSFR_VDDQ_G_S4) U1.AN35(DDR_VDDQ_G_S46) U1.AN36(DDR_VDDQ_G_S47) U1.AU18(DDR_VDDQ_G_S48) U1.AU36(DDR_VDDQ_G_S49) U1.AV10(DDR_VDDQ_G_S410) U1.AV16(DDR_VDDQ_G_S411) U1.AV38(DDR_VDDQ_G_S412) U1.AV44(DDR_VDDQ_G_S413) U1.AY10(DDR_VDDQ_G_S414) U1.AY44(DDR_VDDQ_G_S415) U1.BE1(DDR_VDDQ_G_S416) U1.BE3(DDR_VDDQ_G_S417) U1.BE51(DDR_VDDQ_G_S418) U1.BE53(DDR_VDDQ_G_S419) U1.BG3(DDR_VDDQ_G_S420) U1.BG51(DDR_VDDQ_G_S421) U1.BH4(DDR_VDDQ_G_S422) U1.BH5(DDR_VDDQ_G_S424) U1.BH49(DDR_VDDQ_G_S423) U1.BH50(DDR_VDDQ_G_S425) U1.BJ2(DDR_VDDQ_G_S426) U1.BJ3(DDR_VDDQ_G_S427) U1.BJ5(DDR_VDDQ_G_S429) U1.BJ49(DDR_VDDQ_G_S428) U1.BJ51(DDR_VDDQ_G_S430) U1.BJ52(DDR_VDDQ_G_S431) U11.44(FBVOUT6) U11.46(PVINVTT)
+VSM_VTT: C118.1 C129.2 C130.2 C131.2 C132.2 C244.2 C245.2 C246.2 C247.2 CN1.203(VTT1) CN1.204(VTT2) U11.47(VTT) U11.48(VTTFB)
A6: R144.1 U1.A6(VSS2) U7.2(B)
A_EARPHONE_SEL: J3.6 R339.1 R355.1
AC_IN: CN21.B D21.N F8.2 R493.2
AC_PRESENT: Q8.1(G) R398.2
AC_VREF: C363.1 C365.2 U25.28(VREF)
ADP_IN#: R453.2 U31.71(ADC5/DCD1/GPI5)
AUD_MIC1_IN_L: R336.2 R337.1 R348.2
AUD_MIC1_IN_R: R334.2 R335.1 R347.2
AUD_MIC_IN_L: C377.2 U25.17(MIC2-L(PORT-F-L))
AUD_MIC_IN_R: C373.2 U25.18(MIC2-R(PORT-F-R))
AUDIO_DVDD_IO: C388.2 R343.1 R344.1 U25.9(DVDD-IO)
AUXN_LVDS: C299.1 U16.1(DAUXN)
AUXP_LVDS: C303.1 U16.2(DAUXP)
AXGND: C182.1 C183.1 C184.1 C187.2 C193.1 C194.1 C201.1 C221.1 C233.1 C234.1 C235.1 C243.1 R195.1 R198.1 R200.2 R209.2 R211.2 R582.2 R583.2 U11.52(ANGD)
BH53: R143.1 R596.1 U1.BH53(VSS16) U7.1(A)
BL_ADJ: R260.1 R530.1 U31.25(PWM1/GPA1)
BLCTL_EC: R439.2 R443.1 R542.2 U42.2(B)
BT_ON: R790.2 U31.30(PWM4/GPA4)
BT_RF_KILL_R*: CN26.54(W_DISABLE2* (O)(0/3.3V)) R789.2 R790.1
BUF_PLT_RST#: CN11.4 R126.1 R306.2 R372.2 R428.2 U6.10(B1) U27.2(B)
CLK: R570.2 U11.58(CLK)
CLK_LAN_OE#: Q35.2(S) R27.1 R308.1 U1.AM10(PCIE_CLKREQ0B)
CLK_PCIE_LAN_N: U1.C21(CLK_DIFF_N_0) U22.20(REFCLK_N)
CLK_PCIE_LAN_P: U1.A21(CLK_DIFF_P_0) U22.19(REFCLK_P)
CLK_PCIE_WLAN_N: CN26.49(REFCLKN0) U1.B20(CLK_DIFF_N_1)
CLK_PCIE_WLAN_P: CN26.47(REFCLKP0) U1.C19(CLK_DIFF_P_1)
CLK_WLAN_OE#: Q41.2(S) R26.1 U1.AM12(PCIE_CLKREQ1B)
CLK_WLAN_OE#_M2: CN26.53(CLKREQ0*) R786.1
CLK_WLAN_OE#_MINI: Q41.3(D) R786.2
CORE_PWROK: R587.2 R589.1 U1.G16(COREPWROK)
DATA: R571.2 U11.59(DATA)
DBG_UART1_RXD: Q7.2(S) U1.T52(HV_DDI2_DDC_SDA)
DBG_UART1_TXD: Q6.2(S) U1.T51(HV_DDI2_DDC_SCL)
DDI0_HPD: R14.1 R2984.2 U1.W51(HV_DDI0_HPD)
DDI1_HPD: Q4.3(D) R18.1 U1.R51(HV_DDI1_HPD)
DDR3_DRAM_PWROK: R9.2 R210.1 U1.AV28(DDR3_DRAM_PWROK)
DDR3_VCCA_PWROK: R214.2 R588.1 U1.AV26(DDR3_VCCA_PWROK)
DDR3L_DRAMRST#: CN1.30(RESET#) U1.BA42(DDR3_M0_DRAMRSTB)
DDR3L_EVENT: R149.1 U31.68(ADC2/GPI2)
DMIC_CLK: U25.3(GPIO1/DMIC-CLK)
DMIC_DATA: U25.2(GPIO0/DMIC-DATA)
DP_HPD: Q4.1(G) R19.2 U16.11(HPD)
DRVH1: R204.1 U11.33(DRVH1)
DRVH1_5614561: Q9.1(GATE1) R189.1
DRVH1_R: Q15.1(GATE1) R204.2
DRVH1_R_5614085: R189.2 U10.16(DRVH1)
DRVH2: R201.2 U11.3(DRVH2)
DRVH2_5615145: Q10.8 R190.2
DRVH2_R: Q14.1(GATE1) R201.1
DRVH2_R_5614085: R190.1 U10.10(DRVH2)
DRVH6: R197.2 U11.43(DRVH6)
DRVH6_R: Q13.8 R197.1
DRVL1: R205.1 U11.37(DRVL1)
DRVL1_5614359: Q9.6(G2) R191.1
DRVL1_R: Q15.6(G2) R205.2
DRVL1_R_5614085: R191.2 U10.15(DRVL1)
DRVL2: R202.2 U11.7(DRVL2)
DRVL2_5615173: Q10.3 R192.2
DRVL2_R: Q14.6(G2) R202.1
DRVL2_R_5614085: R192.1 U10.11(DRVL2)
DRVL6: R199.2 U11.39(DRVL6)
DRVL6_R: Q13.3 R199.1
EC_BLEN: R543.1 U31.35(RTS1/GPE5)
EC_IRQB: R407.1 R562.2 U32.8(B3)
EC_MUTE#: R350.2 U26.1(A) U31.28(PWM2/GPA2)
EDID_SCL: R270.1 U16.29(DDC_SCL) U17.6(SCL)
EDID_SDA: R271.1 U16.30(DDC_SDA) U17.5(SDA)
EDP_AUXN: C299.2 U1.K42(DDI1_AUXN)
EDP_AUXP: C303.2 U1.M42(DDI1_AUXP)
EDP_BKLCTL: Q49.1(G) R538.1 U1.P52(PANEL1_BKLTCTL)
EDP_BKLCTL_3P3: Q48.3(D) R259.1 R534.2 R536.2
EDP_BKLEN: Q51.1(G) R544.1 U1.P51(PANEL1_BKLTEN)
EDP_BKLEN_3P3: Q50.3(D) R539.2 R542.1 U42.1(A)
EDP_BKLEN_OUT: R541.2 R543.2 R3094.1 U42.4(Y)
EDP_TXN0: C281.1 U1.H51(DDI1_TXN_0)
EDP_TXN1: C290.1 U1.K52(DDI1_TXN_1)
EDP_TXP0: C287.1 U1.J51(DDI1_TXP_0)
EDP_TXP1: C292.2 U1.K51(DDI1_TXP_1)
EDP_VDDEN: Q31.1(G) U1.R53(PANEL1_VDDEN)
EECS: R300.2 U22.30(EECS)
EEDI: R298.2 U22.32(EEDI)
EEDO: U22.31(LED3/EEDO)
EESK: U22.37(LED1/EESK)
EMMC_CLK: R167.1 U1.M7(SDMMC1_CLK)
EMMC_CMD: R165.1 U1.P6(SDMMC1_CMD)
EMMC_DATA_0: R158.1 U1.M6(SDMMC1_D0)
EMMC_DATA_1: R164.1 U1.M4(SDMMC1_D1)
EMMC_DATA_2: R157.1 U1.P9(SDMMC1_D2)
EMMC_DATA_3: R162.1 U1.P7(SDMMC1_D3_CD_B)
EMMC_DATA_4: R160.1 U1.T6(MMC1_D4_SD_WE)
EMMC_DATA_5: R161.1 U1.T7(MMC1_D5)
EMMC_DATA_6: R159.1 U1.T10(MMC1_D6)
EMMC_DATA_7: R156.1 U1.T12(MMC1_D7)
EMMC_RESET: R166.2 R168.1
ENA: R3094.2 U41.9(ENA)
ENBLT: R541.1 U16.23(ENBLT)
ENPVCC/I2C_ADDR: R272.1 U16.33(ENPVCC/I2C_ADDR)
ENSWREG: R302.2 R303.1 U22.33(ENSWREG)
EVDD10: C348.2 C349.1 R309.1 U22.21(EVDD10)
FAN_BACK: CN25.2 D28.P R2.2 R3.2
FAN_PWMIN: CN25.3 R258.1 U31.24(PWM0/GPA0)
FAN_VCC: C565.2 CN25.1 FB24.1
FB3: R109.2 R821.1 U11.12(FB3)
FB4: C823.2 R842.1 R843.2 U11.23(FB4)
FB5: R844.2 U11.22(FB5)
FBGND2: R826.2 R827.2 U11.1(FBGND2)
FBVOUT1: R563.1 R823.1 U11.29(FBVOUT1)
FBVOUT2: R105.2 R825.1 U11.2(FBVOUT2)
FLASH_TXE: Q5.1(G) R397.2
FMISO: U31.103(FMISO) U34.2(SO/SIO1)
FMOSI: U31.102(FMOSI) U34.5(SI/SIO0)
FSCE#: U31.101(FSCE#) U34.1(CS#)
FSCK: U31.105(FSCK) U34.6(SCLK)
GA20_EC: Q42.3(D) R406.2 R429.2 U31.126(GA20/GPB5)
GL834L_3V3: C700.1 C701.1 C705.1 C708.1 C710.2 FB19.1 FB20.2 R801.1 U95.1(DVDD) U95.19(DVDD33_1) U95.23(DVDD33)
GL850_AVDD: C146.2 C147.2 C148.2 C150.2 C151.2 C152.2 FB1.1 U9.1(AVDD) U9.5(AVDD_1) U9.10(AVDD_2)
GL850G_RST#: C153.2 R174.2 R176.2 U9.13(RESET#)
GL850G_X1: C155.2 U9.6(X1) X4.1
GL850G_X2: C154.2 U9.7(X2) X4.3
GP_CAMERASB08: R227.1 R230.2 U1.Y44(GP_CAMERASB08)
GP_CAMERASB09: R228.1 R232.2 U1.Y42(GP_CAMERASB09)
GP_CAMERASB11: R229.1 R233.2 U1.V40(GP_CAMERASB11)
GPIO_SUS8: R68.1 R77.2 U1.AF51(SEC_GPIO_SUS8)
GPIO_SUS9: R67.1 R76.1 U1.AF52(SEC_GPIO_SUS9)
GPIO_SUS10: R66.2 R75.1 U1.AE51(SEC_GPIO_SUS10)
GPIO_SUS11: R78.2 U1.AC51(SEC_GPIO_SUS11)
GPO: R317.2 U22.38(GPO/SMBALERT)
H_PROCHOT#: C428.1 R108.1 U1.AD50(PROCHOT_B) U33.4(Y)
H_RCIN#: D11.P R412.2 R414.1 R431.1 U30.9(B2)
HD: R41.1 U1.U3(FST_SPI_D3) U2.7(NC(DQ3)) U4.7(RESET#/SIO3)
HDA_BITCLK: C389.2 R31.2 U25.6(BCLK)
HDA_RST#: R30.2 R358.1 R359.2 U25.11(RESETB)
HDA_SDATAIN0: C391.2 R32.2 U25.8(SDA TA-IN)
HDA_SDATAOUT: C392.2 R34.2 U25.5(SDATA-OUT)
HDA_SYNC: C390.2 R33.2 U25.10(SYNC)
HP_OUT_L: C396.1 R332.1 R352.2 R356.1
HP_OUT_R: C397.1 R331.1 R354.2 R357.1
HSON: C346.2 U22.23(HSON)
HSOP: C347.2 U22.22(HSOP)
HUB_USB_PN1: CN26.5(USB_D-) U9.2(DM2)
HUB_USB_PN2: U9.27(DM1) U95.2(DM)
HUB_USB_PP1: CN26.3(USB_D+) U9.3(DP2)
HUB_USB_PP2: U9.28(DP1) U95.3(DP)
I2C_CLK0: R401.2 U31.110(SMCLK0/GPB3)
I2C_CLK1: R396.2 R423.2 U31.115(SMCLK1/GPC1)
I2C_CLK2: R405.2 U31.117(SMCLK2/PECI/GPF6)
I2C_CLK2_LVDS: R276.2 R423.1 U16.25(CSCL/MSCL) U18.6(SCL)
I2C_CLK3: R392.2 U31.94(CRX1/SIN1/SMCLK3/GPH1/ID1)
I2C_DATA0: R402.2 U31.111(SMDAT0/GPB4)
I2C_DATA1: R399.2 R424.2 U31.116(SMDAT1/GPC2)
I2C_DATA2: R408.2 U31.118(SMDAT2/PECIRQT#/GPF7)
I2C_DATA2_LVDS: R277.2 R424.1 U16.24(CSDA/MSDA) U18.5(SDA)
I2C_DATA3: R394.2 U31.95(CTX1/SOUT1/GPH2/SMDAT3/ID2)
IINA: CN22.2 R3101.1 R3102.1 R3103.1 R3104.1
IINA0: J5.1 R345.1 R3101.2 U41.1(ISEN  1)
IINA1: J5.2 R345.2 R3102.2 U41.2(ISEN 2)
IINA2: R367.2 R3089.1 R3095.1 R3103.2 U41.4(ISEN  3)
IINA3: R3090.1 R3095.2 R3097.2 R3104.2 U41.5(ISEN 4)
INNER_MIC: B1.1(D) C373.1 C377.1 CN7.2 R333.2
IRQB: Q52.2(S) R407.2 R569.1 U32.4(A3)
ISETA: CN40.2 CN40.4 CN40.6 CN40.8 R465.2 R466.2 R638.2 R648.1 R754.1 R3098.2 R3099.2 U41.6(ISET)
ISOLATEB: R305.1 R307.1 U22.26(ISOLATEB)
ISW: R3091.2 U41.10(ISW)
IT8928_VSS: R452.1 U31.104(DSR0#/GPG6/FIOO3)
KBC_FAN_SPEED: C1.2 Q1.3(OUT) R435.1 R584.2
L_OUT+: CN10.2 R362.1
L_OUT-: CN10.1 R363.1
LAN_CMT: R322.2 U23.11(CMT)
LAN_CMT1: R325.2 U24.11(CMT)
LAN_CT: R321.2 U23.14(CT3)
LAN_CT1: R323.2 U24.14(CT3)
LAN_N1: C352.1 C353.2 C354.2 C355.1 R321.1 R322.1 R323.1 R324.2 R325.1 R327.2 R328.2 R329.2
LAN_TX0N: FIL1.1(UNB) R314.1 U23.9(TX-)
LAN_TX0P: FIL1.4(GND) R312.1 U23.10(TX+)
LAN_TX1N: FIL2.1(UNB) R316.1 U23.15(RX-)
LAN_TX1P: FIL2.4(GND) R315.1 U23.16(RX+)
LAN_TX2N: FIL3.4(GND) R319.1 R327.1 U24.9(TX-)
LAN_TX2P: FIL3.1(UNB) R318.1 R324.1 U24.10(TX+)
LAN_TX3N: FIL4.1(UNB) R326.1 R328.1 U24.15(RX-)
LAN_TX3P: FIL4.4(GND) R320.1 R329.1 U24.16(RX+)
LAN_VDDEN_EC: R301.2 U21.3(EN/ENB) U31.29(PWM3/GPA3)
LANWAKEB: R304.1 U22.28(LANWAKEB)
LAO1_CLKN: CN35.8 U16.35(TCK1N)
LAO1_CLKP: CN35.9 U16.34(TCK1P)
LAO1_DATAN0: CN35.24 U16.42(TA1N)
LAO1_DATAN1: CN35.2 U16.40(TB1N)
LAO1_DATAN2: CN35.5 U16.37(TC1N)
LAO1_DATAN3: CN35.10 U16.32(TD1N)
LAO1_DATAP0: CN35.23 U16.41(TA1P)
LAO1_DATAP1: CN35.3 U16.39(TB1P)
LAO1_DATAP2: CN35.6 U16.36(TC1P)
LAO1_DATAP3: CN35.11 U16.31(TD1P)
LAO_CLKN: CN35.30 U16.47(TCK0N)
LAO_CLKP: CN35.29 U16.46(TCK0P)
LAO_DATAN0: CN35.39 U16.54(TA0N)
LAO_DATAN1: CN35.36 U16.52(TB0N)
LAO_DATAN2: CN35.33 U16.49(TC0N)
LAO_DATAN3: CN35.27 U16.44(TD0N)
LAO_DATAP0: CN35.38 U16.53(TA0P)
LAO_DATAP1: CN35.35 U16.51(TB0P)
LAO_DATAP2: CN35.32 U16.48(TC0P)
LAO_DATAP3: CN35.26 U16.43(TD0P)
LCD_VCC: C283.2 C284.1 C942.2 CN35.13 CN35.14 CN35.15 U15.1(VOUT)
LDO2-CAP: C376.2 U25.39(LDO2-CAP)
LDR: R606.1 U41.11(LDR)
LED_ON: U31.34(PWM7/GPA7/RIG1)
LL1: C165.2 D2.N L1.2 Q9.7(S1/D2) U10.18(SW1)
LL2: C166.1 D3.N L2.1 Q10.5 Q10.6 Q10.7 U10.8(SW2)
LPC_AD0: CN11.8 U1.M3(MF_LPC_AD0) U31.10(LAD0/GPM0)
LPC_AD1: CN11.7 U1.M2(MF_LPC_AD1) U31.9(LAD1/GPM1)
LPC_AD2: CN11.6 U1.N3(MF_LPC_AD2) U31.8(LAD2/GPM2)
